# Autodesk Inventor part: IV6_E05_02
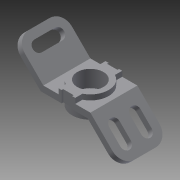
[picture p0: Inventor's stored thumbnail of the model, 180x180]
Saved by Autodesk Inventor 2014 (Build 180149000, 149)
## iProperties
Shininess: 64.0
Length Units: 11269
Angle Units: 11279
Time Units: 11290
Mass Units: 11283
Length Display Precision: 3
Angle Display Precision: 2
Created: 2002-08
Part Number: IV6_E05_02
Document SubType Name: Modeling
Designer: t_munrn
Density: 1 g/cm^3
Material: Generic
Appearance: Default
Density: 0.0
Volumn: 0.0
Area: 0.0
PropertySet Name: Model Information
Control State: 0
Master: False
Checked Out: False
Author: t_munrn
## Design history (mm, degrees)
sketch "Sketch1"
  geometry: L1 (-45, 0)-(45, 0); L2 (0, 0)-(0, -12); L3 (-45, 0)-(-98.033, 53.033); L4 (-98.033, 53.033)-(-106.518, 44.548); L5 (-106.518, 44.548)-(-49.971, -12); L6 (-49.971, -12)-(40.029, -12); L7 (40.029, -12)-(96.619, -68.589); L8 (96.619, -68.589)-(105.104, -60.104); L9 (105.104, -60.104)-(45, 0); 1 further point
  constraints: 18 end point, 4 perpendicular, 3 parallel, 2 equal length, 1 coincident, 1 horizontal, 1 midpoint, 1 point on line
  dimensions: "d0" = 90 distance of L1.start L1.end; "d1" = 85 distance of L8.end L1.end; "d2" = 12 distance of L3.end L4.end; "d3" = 75 distance of L1.start L3.end; "d4" = 45 deg angle of L5 L6
extrude "Extrusion1" new body sketch "Sketch1" stored distance "d5" = 90; taper "d6" = 0 deg
sketch "Sketch2"
  geometry: C1 r 35 at (45, 45); 1 further point
  constraints: 1 centre point, 1 coincident
  dimensions: "d7" = 70 diameter of C1
extrude "Extrusion2" join sketch "Sketch2" distance "d8" = 10; taper "d9" = 0 deg
sketch "Sketch6"
  geometry: C1 r 35 at (49.971, -45) reference
extrude "Extrusion3" join sketch "Sketch6" distance "d26" = 20; taper "d27" = 0 deg
sketch "Sketch3"
  geometry: L1 (-45, 0)-(45, 0) reference; L2 (-35, 10)-(35, 10) reference; L3 (0, 10)-(0, 0); L4 (-16, 10)-(-16, 0); L5 (16, 10)-(16, 0)
  constraints: 6 end point, 4 point on line, 2 midpoint, 2 perpendicular
  dimensions: "d10" = 16 distance between parallel lines of L4 L3; "d11" = 16 distance between parallel lines of L5 L3
extrude "Extrusion4" join sketch "Sketch3" stored distance "d12" = 13; taper "d13" = 0 deg
sketch "Sketch4"
  geometry: A1 r 35 centre (45, 45) between (29, 76.129) and (29, 13.871) reference
hole "Hole1" sketch "Sketch4" at (45, 45) diameter "d14" = 25; stored, may be unused: countersink angle "d18" = 82 deg, drill point angle "d20" = 118 deg; dims "d15" = 6, "d16" = 50, "d17" = 32, "d19" = 8
sketch "Sketch5"
  geometry: L1 (29, 90)-(61, 90) reference; L2 (29, 76.129)-(29, 90) reference; L3 (35, 90)-(35, 87); L4 (35, 87)-(55, 87); L5 (55, 87)-(55, 90); L6 (45, 87)-(45, 90); L7 (61, 76.129)-(61, 90) reference
  constraints: 8 end point, 2 midpoint, 2 parallel, 2 perpendicular, 2 point on line
  dimensions: "d22" = 3 distance of L4.end L5.end; "d28" = 6 distance between parallel lines of L7 L5
extrude "Extrusion5" cut sketch "Sketch5" stored distance "d23" = 13; taper "d24" = 0 deg
fillet "Fillet1" dims "d25" = 25
sketch "Sketch7"
  geometry: L1 (60, 65)-(60, 25); L2 (40, 65)-(40, 25); A1 r 25 centre (50, 25) between (50, 0) and (75, 25) reference; A2 r 25 centre (50, 65) between (75, 65) and (50, 90) reference; A3 r 10 centre (50, 65) between (60, 65) and (40, 65); A4 r 10 centre (50, 25) between (60, 25) and (40, 25)
  constraints: 4 end point, 4 point on circle, 4 tangent, 2 centre point, 2 coincident, 1 equal radius
  dimensions: "d29" = 20 diameter of A4
extrude "Extrusion6" cut sketch "Sketch7" stored distance "d30" = 20; taper "d31" = 0 deg
sketch "Sketch8"
  geometry: L1 (-60, 75)-(-30, 75); L2 (-60, 55)-(-30, 55); A1 r 25 centre (-60, 65) between (-60, 90) and (-85, 65) reference; A2 r 10 centre (-60, 65) between (-60, 75) and (-60, 55); A3 r 10 centre (-30, 65) between (-30, 75) and (-30, 55)
  constraints: 4 end point, 4 point on circle, 4 tangent, 2 centre point, 1 coincident, 1 equal radius, 1 horizontal alignment
  dimensions: "d32" = 20 diameter of A2; "d33" = 30 distance of L1.start L1.end
extrude "Extrusion7" cut sketch "Sketch8" stored distance "d34" = 20; taper "d35" = 0 deg
mirror "Mirror1"
body "Solid1"
